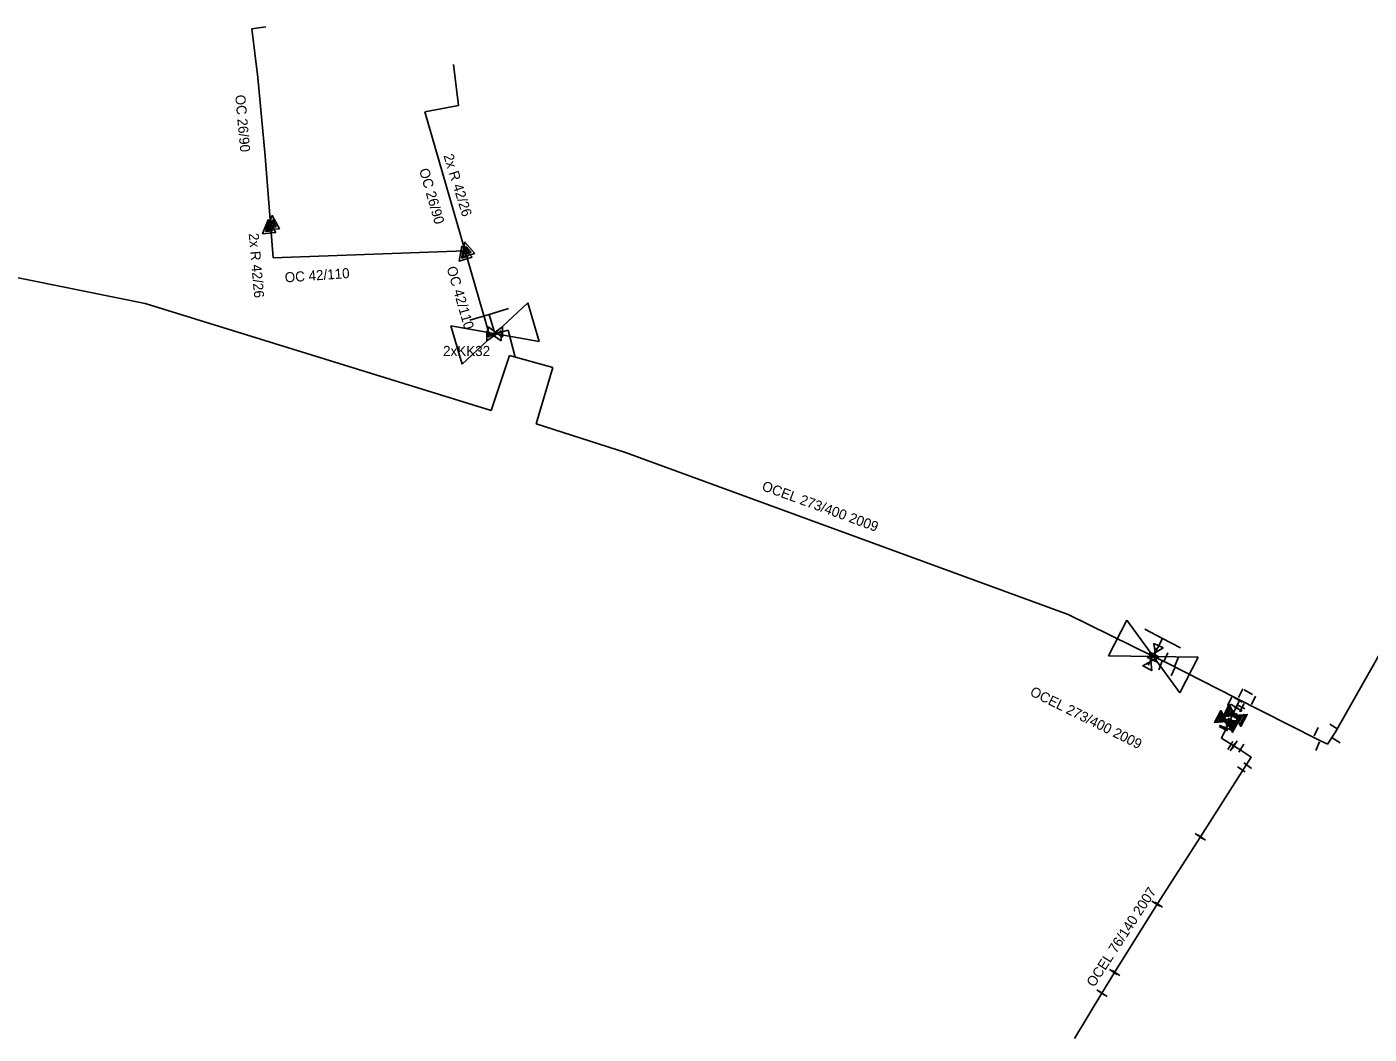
# Model space of a CAD drawing. Extents: x -642943 to -623314, y -1138561 to -1113539.
# Drawn here: x -642216.7 to -642116.4, y -1115444.2 to -1115369 of the extents above; entities that cross this region are included whole.
import ezdxf

# ---------------------------------------------------------------- set-up
doc = ezdxf.new("R2010")
doc.units = 0
for name, color, linetype in [('horkovod armatury', 7, 'Continuous'), ('horkovod dimenze', 7, 'Continuous'), ('horkovod předisol', 7, 'Continuous'), ('horkovod sváry', 7, 'Continuous'), ('horkovod trasa', 7, 'Continuous')]:
    doc.layers.add(name, color=color, linetype=linetype)

# ---------------------------------------------------------------- blocks, each defined once
blk = doc.blocks.new('SPH')
at = {"layer": 'horkovod sváry'}
blk.add_line((0, -0.035), (0, 0.035), dxfattribs=at)
blk = doc.blocks.new('SPH_1')
at = {"layer": 'horkovod sváry'}
blk.add_line((0, -0.035), (0, 0.035), dxfattribs=at)
blk = doc.blocks.new('SREDU')
at = {"layer": 'horkovod armatury'}
for points in [[(-0.05, -0.05), (0.051, 0), (-0.05, 0.05), (-0.05, -0.05)], [(-0.034, -0.025), (0.018, 0), (-0.034, 0.025), (-0.034, -0.025)], [(-0.025, -0.012), (0.001, 0), (-0.025, 0.012), (-0.025, -0.012)]]:
    blk.add_lwpolyline(points, dxfattribs=at)
blk = doc.blocks.new('SSOUP')
at = {"layer": 'horkovod armatury'}
for p, q in [((-0.038, 0.054), (0.038, -0.054)), ((0.038, 0.054), (-0.038, -0.054)), ((-0.038, 0.054), (0.038, 0.054)), ((-0.038, -0.054), (0.038, -0.054))]:
    blk.add_line(p, q, dxfattribs=at)
blk = doc.blocks.new('KULVEN')
at = {"layer": 'horkovod armatury'}
for p, q in [((-0.066, -0.044), (-0.066, 0.044)), ((-0.053, -0.035), (-0.053, 0.035)), ((-0.04, -0.027), (-0.04, 0.027)), ((-0.027, -0.018), (-0.027, 0.018)), ((-0.013, -0.009), (-0.013, 0.009)), ((0.014, -0.009), (0.014, 0.009)), ((0.027, -0.018), (0.027, 0.018)), ((0.037, -0.025), (0.037, 0.025)), ((0.049, -0.033), (0.049, 0.033)), ((0.063, -0.042), (0.063, 0.042))]:
    blk.add_line(p, q, dxfattribs=at)
blk.add_lwpolyline([(0, 0), (0.076, 0.051), (0.076, -0.051), (-0.077, 0.051), (-0.076, -0.051), (0, 0)], dxfattribs=at)
blk = doc.blocks.new('SOUP')
at = {"layer": 'horkovod armatury'}
blk.add_lwpolyline([(0, 0), (0.077, 0.051), (0.076, -0.051), (-0.077, 0.051), (-0.077, -0.051), (0, 0)], dxfattribs=at)
blk = doc.blocks.new('SCH_01_107')
at = {"layer": 'horkovod armatury'}
for p, q in [((10, 5), (-10, -5)), ((-10, -5), (-10, 5)), ((-10, 5), (10, -5)), ((-5, 5), (0, 5)), ((0, 5), (0, 0)), ((5, 5), (0, 5)), ((10, -5), (10, 5))]:
    blk.add_line(p, q, dxfattribs=at)
blk = doc.blocks.new('SCH_01_108')
at = {"layer": 'horkovod armatury'}
for p, q in [((10, 5), (-10, -5)), ((-10, -5), (-10, 5)), ((-10, 5), (10, -5)), ((-5, 5), (0, 5)), ((0, 5), (0, 0)), ((5, 5), (0, 5)), ((10, -5), (10, 5))]:
    blk.add_line(p, q, dxfattribs=at)

msp = doc.modelspace()

# ---------------------------------------------------------------- linework, layer by layer
at = {"layer": 'horkovod armatury'}
for centre in [(-642126.43, -1115420.42), (-642127.05, -1115420.86)]:
    msp.add_circle(centre, 0.15, dxfattribs=at)
at = {"layer": 'horkovod předisol'}
for p, q in [((-642199.89, -1115369.12), (-642198.83, -1115368.97)), ((-642184.45, -1115374.84), (-642184.81, -1115371.79)), ((-642186.96, -1115375.33), (-642184.45, -1115374.84)), ((-642186.96, -1115375.33), (-642182.13, -1115392)), ((-642183.95, -1115385.71), (-642198.28, -1115386.22)), ((-642182.13, -1115392), (-642180.74, -1115391.64)), ((-642180.21, -1115393.65), (-642180.74, -1115391.64)), ((-642180.65, -1115393.53), (-642182, -1115397.64)), ((-642177.39, -1115394.42), (-642180.65, -1115393.53)), ((-642178.64, -1115398.64), (-642177.39, -1115394.42)), ((-642187.17, -1115396.04), (-642182, -1115397.64))]:
    msp.add_line(p, q, dxfattribs=at)
for points in [[(-642199.89, -1115369.12), (-642199.43, -1115372.76), (-642198.89, -1115378.63), (-642198.28, -1115386.22)], [(-642119.54, -1115422.55), (-642118.96, -1115421.69), (-642113.07, -1115411.27), (-642110.18, -1115406.19), (-642104.31, -1115395.76), (-642103.82, -1115394.93)], [(-642178.64, -1115398.64), (-642171.97, -1115400.78), (-642138.92, -1115412.88), (-642132.58, -1115415.98)], [(-642132.58, -1115415.98), (-642131.38, -1115416.56), (-642126.46, -1115419.08), (-642120.3, -1115422.19), (-642119.54, -1115422.55)], [(-642126.11, -1115419.26), (-642126.9, -1115420.97), (-642127.46, -1115422.1), (-642126.06, -1115422.98), (-642125.24, -1115423.54), (-642125.76, -1115424.34), (-642129.03, -1115429.48), (-642132.26, -1115434.51), (-642135.45, -1115439.62), (-642136.4, -1115441.16), (-642138.44, -1115444.54)]]:
    msp.add_lwpolyline(points, dxfattribs=at)
at = {"layer": 'horkovod trasa'}
for p, q in [((-642199.89, -1115369.12), (-642198.83, -1115368.97)), ((-642184.45, -1115374.84), (-642184.81, -1115371.79)), ((-642186.96, -1115375.33), (-642184.45, -1115374.84)), ((-642186.96, -1115375.33), (-642182.13, -1115392)), ((-642245.17, -1115382.12), (-642207.84, -1115389.64)), ((-642183.95, -1115385.71), (-642198.28, -1115386.22)), ((-642207.84, -1115389.64), (-642187.17, -1115396.04)), ((-642182.13, -1115392), (-642180.74, -1115391.64)), ((-642180.21, -1115393.65), (-642180.74, -1115391.64)), ((-642180.65, -1115393.53), (-642182, -1115397.64)), ((-642177.39, -1115394.42), (-642180.65, -1115393.53)), ((-642178.64, -1115398.64), (-642177.39, -1115394.42)), ((-642187.17, -1115396.04), (-642182, -1115397.64))]:
    msp.add_line(p, q, dxfattribs=at)
for points in [[(-642199.89, -1115369.12), (-642199.43, -1115372.76), (-642198.89, -1115378.63), (-642198.28, -1115386.22)], [(-642119.54, -1115422.55), (-642118.96, -1115421.69), (-642113.07, -1115411.27), (-642110.18, -1115406.19), (-642104.31, -1115395.76), (-642103.82, -1115394.93)], [(-642178.64, -1115398.64), (-642171.97, -1115400.78), (-642138.92, -1115412.88), (-642132.58, -1115415.98)], [(-642132.58, -1115415.98), (-642131.38, -1115416.56), (-642126.46, -1115419.08), (-642120.3, -1115422.19), (-642119.54, -1115422.55)], [(-642126.11, -1115419.26), (-642126.9, -1115420.97), (-642127.46, -1115422.1), (-642126.06, -1115422.98), (-642125.24, -1115423.54), (-642125.76, -1115424.34), (-642129.03, -1115429.48), (-642132.26, -1115434.51), (-642135.45, -1115439.62), (-642136.4, -1115441.16), (-642138.44, -1115444.54)]]:
    msp.add_lwpolyline(points, dxfattribs=at)

# ---------------------------------------------------------------- block references
at = {"layer": 'horkovod armatury'}
for name, p, xscale, yscale, rotation in [('SREDU', (-642198.34, -1115383.58), 10.000004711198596, 10.000004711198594, 92.08447046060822), ('SREDU', (-642198.34, -1115383.58), 10.000004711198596, 10.000004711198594, 92.08447046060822), ('SREDU', (-642198.62, -1115383.89), 9.9999987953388, 9.999998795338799, 94.77385603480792), ('SREDU', (-642198.62, -1115383.89), 9.9999987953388, 9.999998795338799, 94.77385603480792), ('SREDU', (-642184.06, -1115385.85), 9.999995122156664, 9.999995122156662, 106.86021708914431), ('SREDU', (-642184.06, -1115385.85), 9.999995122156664, 9.999995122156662, 106.86021708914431), ('SREDU', (-642183.83, -1115385.55), 9.999989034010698, 9.999989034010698, 105.28032087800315), ('SREDU', (-642183.84, -1115385.55), 9.999989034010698, 9.999989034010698, 105.28032087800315), ('SCH_01_107', (-642181.73, -1115391.89), 0.29998386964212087, 0.299983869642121, 16.493938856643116), ('SSOUP', (-642181.8, -1115392.05), 10, 10, 90), ('SSOUP', (-642181.8, -1115392.05), 10, 10, 90), ('SSOUP', (-642181.69, -1115391.77), 10, 10, 90), ('SSOUP', (-642181.69, -1115391.77), 10, 10, 90), ('SCH_01_108', (-642132.55, -1115416), 0.29999733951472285, 0.2999973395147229, -27.38566660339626), ('SOUP', (-642132.41, -1115415.73), 7.499972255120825, 7.499972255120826, -114.76351262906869), ('SOUP', (-642132.74, -1115416.37), 7.499985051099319, 7.499985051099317, -117.50659949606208), ('KULVEN', (-642127.06, -1115420.86), 9.999996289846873, 9.999996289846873, -28.16389116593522), ('KULVEN', (-642126.45, -1115420.42), 10.000012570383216, 10.000012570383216, -28.51031718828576)]:
    msp.add_blockref(name, p, dxfattribs=dict(at, xscale=xscale, yscale=yscale, rotation=rotation))
at = {"layer": 'horkovod sváry'}
for name, p, xscale, yscale, rotation in [('SPH_1', (-642132.78, -1115416.35), 9.999975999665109, 9.999975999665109, -27.751643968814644), ('SPH', (-642132.44, -1115415.71), 9.999996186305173, 9.999996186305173, -23.157566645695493), ('SPH', (-642132.01, -1115416.69), 9.999981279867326, 9.999981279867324, -21.246651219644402), ('SPH_1', (-642131.61, -1115416.06), 10.000003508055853, 10.000003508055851, -24.873344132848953), ('SPH', (-642130.8, -1115416.38), 9.999979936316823, 9.999979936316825, -23.526363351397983), ('SPH', (-642131.07, -1115417.13), 9.999989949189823, 9.999989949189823, -25.125079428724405), ('SPH', (-642126.84, -1115419.37), 9.999992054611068, 9.999992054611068, -27.498642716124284), ('SPH_1', (-642126.22, -1115419.25), 10.000001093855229, 10.00000109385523, 58.54302669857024), ('SPH_1', (-642126.03, -1115418.75), 9.999992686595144, 9.999992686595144, -26.28405431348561), ('SPH_1', (-642125.45, -1115418.68), 10.000019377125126, 10.000019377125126, 60.97348701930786), ('SPH_1', (-642125.07, -1115419.28), 9.999982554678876, 9.999982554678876, -25.441711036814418), ('SPH_1', (-642126.85, -1115420.3), 10.000005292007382, 10.00000529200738, 63.67967208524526), ('SPH_1', (-642126.49, -1115419.73), 10.000001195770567, 10.000001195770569, 61.641654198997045), ('SPH_1', (-642126.21, -1115419.93), 10.000015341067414, 10.000015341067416, 61.26020470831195), ('SPH_1', (-642126.03, -1115419.76), 9.999974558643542, 9.999974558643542, 61.68128231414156), ('SPH_1', (-642125.93, -1115419.83), 9.999987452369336, 9.999987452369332, -26.863707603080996), ('SPH', (-642127.32, -1115421.4), 10.000011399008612, 10.000011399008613, 62.50923515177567), ('SPH', (-642127.3, -1115421.3), 9.999999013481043, 9.999999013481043, 61.35596074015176), ('SPH', (-642126.94, -1115421.42), 9.999997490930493, 9.99999749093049, 64.2782047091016), ('SPH_1', (-642126.84, -1115421.27), 9.999979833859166, 9.999979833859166, 61.104484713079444), ('SPH_1', (-642126.66, -1115420.8), 9.999980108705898, 9.999980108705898, 60.28788089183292), ('SPH', (-642120.38, -1115421.63), 10.000013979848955, 10.000013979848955, -25.836711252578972), ('SPH_1', (-642119.07, -1115421.25), 10.000009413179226, 10.000009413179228, 58.03435190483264), ('SPH_1', (-642126.8, -1115422.66), 9.999990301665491, 9.999990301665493, -32.05003933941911), ('SPH_1', (-642126.47, -1115422.6), 9.99999339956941, 9.99999339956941, -31.32166746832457), ('SPH_1', (-642120.27, -1115422.71), 10.000016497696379, 10.000016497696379, -23.06062996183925), ('SPH', (-642118.9, -1115422.27), 10.000016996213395, 10.000016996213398, 58.48770552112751), ('SPH_1', (-642126.63, -1115422.77), 9.999979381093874, 9.999979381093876, -31.781960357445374), ('SPH_1', (-642125.98, -1115422.85), 9.99999465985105, 9.999994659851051, -31.527396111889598), ('SPH_1', (-642125.97, -1115424.44), 9.999972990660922, 9.99997299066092, 55.889617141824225), ('SPH', (-642125.5, -1115424.16), 10.000002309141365, 10.000002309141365, 52.98917599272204), ('SPH', (-642129.13, -1115429.43), 9.999971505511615, 9.999971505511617, 55.37210728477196), ('SPH', (-642128.93, -1115429.53), 9.999984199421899, 9.9999841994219, 55.23326592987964), ('SPH', (-642132.36, -1115434.47), 9.999981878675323, 9.999981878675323, 56.05737495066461), ('SPH', (-642132.15, -1115434.55), 10.000030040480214, 10.000030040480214, 55.786980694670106), ('SPH', (-642135.54, -1115439.57), 10.00000104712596, 10.000001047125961, 56.920800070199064), ('SPH', (-642135.34, -1115439.65), 9.999992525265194, 9.999992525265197, 56.773537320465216), ('SPH', (-642136.48, -1115441.11), 9.999988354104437, 9.999988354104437, 56.21676844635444), ('SPH', (-642136.3, -1115441.21), 9.99999427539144, 9.999994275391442, 56.245997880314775)]:
    msp.add_blockref(name, p, dxfattribs=dict(at, xscale=xscale, yscale=yscale, rotation=rotation))

# ---------------------------------------------------------------- texts
at = {"layer": 'horkovod dimenze'}
for s, rotation, p in [('OC 26/90', 275.1483, (-642201.13, -1115374.08)), ('2x R 42/26', 287.3365, (-642185.58, -1115378.59)), ('OC 26/90', 286.209, (-642187.4, -1115379.66)), ('2x R 42/26', 274.9697, (-642200.12, -1115384.42)), ('OC 42/110', 3.9567, (-642197.4, -1115388.07)), ('OC 42/110', 286.209, (-642185.34, -1115386.98)), ('OCEL 273/400 2009', 339.9475, (-642161.85, -1115403.57)), ('OCEL 273/400 2009', 333.5793, (-642141.83, -1115418.88)), ('OCEL 76/140 2007', 56.9406, (-642136.97, -1115440.76))]:
    msp.add_text(s, height=0.75, rotation=rotation, dxfattribs=at).set_placement(p)
msp.add_text('2xKK32', height=0.75, dxfattribs=at).set_placement((-642185.6, -1115393.56))

doc.saveas('drawing.dxf')
